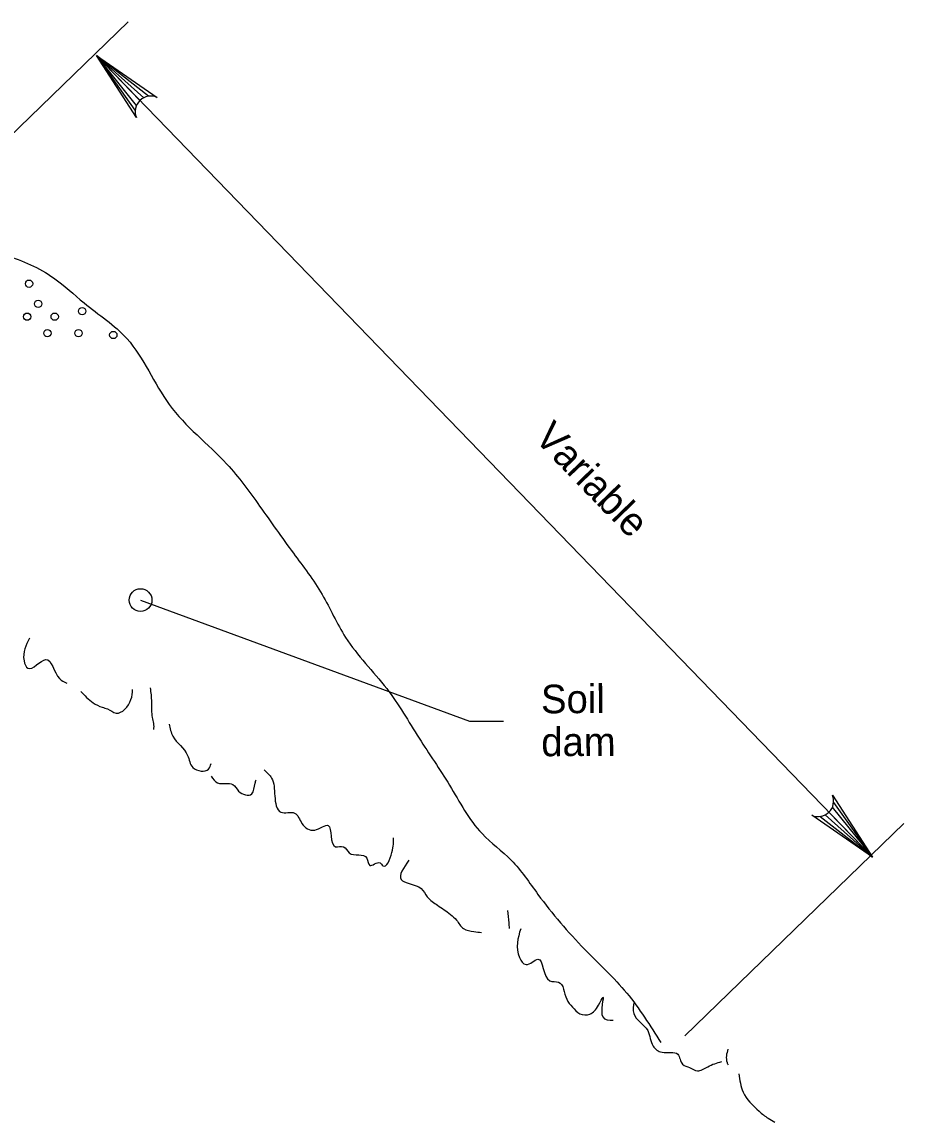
# Model space of a CAD drawing. Extents: x 3862.5 to 3891, y 3400.3 to 3419.7.
# Drawn here: x 3886.65 to 3890.97, y 3400.47 to 3405.86 of the extents above; entities that cross this region are included whole.
import ezdxf

# ---------------------------------------------------------------- set-up
doc = ezdxf.new("R2010")
doc.units = 0
doc.layers.add('DR_X_Trench_Drain', color=7, linetype='Continuous')
doc.layers.add('GT_X_Coal_Seam_1', color=7, linetype='Continuous')

msp = doc.modelspace()

# ---------------------------------------------------------------- linework, layer by layer
at = {"layer": 'DR_X_Trench_Drain'}
for centre, radius in [((3886.6838, 3404.5754), 0.0179), ((3886.7286, 3404.4768), 0.0179), ((3886.9439, 3404.4409), 0.0179), ((3886.6748, 3404.414), 0.0179), ((3886.8093, 3404.414), 0.0179), ((3886.7735, 3404.3333), 0.0179), ((3886.9259, 3404.3333), 0.0179), ((3887.0963, 3404.3243), 0.0179), ((3887.2295, 3403.0269), 0.0557)]:
    msp.add_circle(centre, radius, dxfattribs=at)
for points in [[(3882.5038, 3404.742), (3882.844, 3404.7208), (3883.6368, 3404.6299), (3884.1822, 3404.5789), (3884.7276, 3404.6302), (3885.5788, 3404.707), (3886.0457, 3404.7397), (3886.3113, 3404.759), (3886.569, 3404.715), (3886.8043, 3404.6035), (3886.9533, 3404.4814), (3887.1626, 3404.3064), (3887.3698, 3403.9842), (3887.6515, 3403.6928), (3887.8125, 3403.4869), (3887.9775, 3403.2565), (3888.1183, 3403.0547), (3888.233, 3402.8444), (3888.4342, 3402.5937), (3888.5931, 3402.351), (3888.742, 3402.1205), (3888.901, 3401.8839), (3889.0438, 3401.7537), (3889.1746, 3401.5865), (3889.404, 3401.3174), (3889.6092, 3401.1035), (3889.7762, 3400.8609)], [(3886.6853, 3402.8404), (3886.6592, 3402.7299), (3886.6773, 3402.6932), (3886.7658, 3402.7364), (3886.8322, 3402.6427), (3886.8685, 3402.6203)], [(3886.937, 3402.5797), (3886.9972, 3402.5247), (3887.0416, 3402.5024), (3887.0677, 3402.4943), (3887.11, 3402.474), (3887.1825, 3402.5397), (3887.1905, 3402.5888)], [(3887.277, 3402.5973), (3887.2831, 3402.5278), (3887.2871, 3402.4522), (3887.2931, 3402.4235), (3887.2931, 3402.3929)], [(3887.3696, 3402.4198), (3887.3877, 3402.3605), (3887.4601, 3402.2668), (3887.4862, 3402.2075), (3887.5627, 3402.1997), (3887.5748, 3402.2264)], [(3887.8343, 3402.1967), (3887.8706, 3402.1559), (3887.8867, 3402.068), (3887.9168, 3401.9884), (3887.9833, 3401.9847), (3888.0195, 3401.9337), (3888.0818, 3401.9012), (3888.1483, 3401.9239), (3888.1845, 3401.8198), (3888.2227, 3401.8199), (3888.251, 3401.7894), (3888.3375, 3401.7632), (3888.3515, 3401.7284), (3888.4018, 3401.7409), (3888.416, 3401.7267), (3888.4602, 3401.7923), (3888.4682, 3401.8638)], [(3887.5748, 3402.165), (3887.607, 3402.1324), (3887.6815, 3402.1245), (3887.7096, 3402.0919), (3887.774, 3402.0779), (3887.7901, 3402.131), (3887.7961, 3402.1474)], [(3888.5427, 3401.7537), (3888.5045, 3401.6595), (3888.6031, 3401.6149), (3888.6332, 3401.5742), (3888.6836, 3401.5334), (3888.746, 3401.4887), (3888.7761, 3401.4602), (3888.8103, 3401.4194), (3888.8606, 3401.4053), (3888.8988, 3401.3993)], [(3889.0257, 3401.5082), (3889.0317, 3401.4469), (3889.0337, 3401.4203)], [(3889.0901, 3401.4184), (3889.084, 3401.2773), (3889.1162, 3401.2427), (3889.1746, 3401.2695), (3889.2328, 3401.1634), (3889.2751, 3401.1574), (3889.3153, 3401.0738), (3889.3436, 3401.035), (3889.3797, 3401.0024), (3889.4281, 3401.0005), (3889.4703, 3401.0437), (3889.4925, 3401.0827), (3889.4925, 3400.9865), (3889.5427, 3400.9704)], [(3889.6455, 3401.0608), (3889.6435, 3401.0035), (3889.7118, 3400.9199), (3889.738, 3400.8444), (3889.7822, 3400.8139), (3889.8587, 3400.8039), (3889.8828, 3400.7549), (3889.9171, 3400.7388), (3889.9553, 3400.7225), (3890.0056, 3400.7432), (3890.074, 3400.768)], [(3890.1042, 3400.8294), (3890.1002, 3400.764), (3890.1062, 3400.7518)], [(3890.1586, 3400.709), (3890.1787, 3400.6192), (3890.2571, 3400.5254), (3890.3013, 3400.4908), (3890.3336, 3400.4725)]]:
    msp.add_spline(points, degree=3, dxfattribs=at)
at = {"layer": 'GT_X_Coal_Seam_1'}
for p, q in [((3886.0953, 3404.8174), (3887.1682, 3405.8562)), ((3887.0136, 3405.6922), (3890.8118, 3401.769)), ((3887.2268, 3405.4719), (3887.0136, 3405.6922)), ((3887.2101, 3405.4479), (3887.0136, 3405.6922)), ((3887.2037, 3405.4245), (3887.0136, 3405.6922)), ((3887.2453, 3405.4854), (3887.0136, 3405.6922)), ((3887.2688, 3405.493), (3887.0136, 3405.6922)), ((3890.6218, 3402.0365), (3890.8118, 3401.769)), ((3890.5566, 3401.9682), (3890.8118, 3401.769)), ((3890.5801, 3401.9758), (3890.8118, 3401.769)), ((3890.5987, 3401.9892), (3890.8118, 3401.769)), ((3890.6155, 3402.0133), (3890.8118, 3401.769)), ((3889.8935, 3400.8943), (3890.9663, 3401.933))]:
    msp.add_line(p, q, dxfattribs=at)
for points in [[(3887.2091, 3405.3884), (3887.0136, 3405.6922), (3887.3108, 3405.4869)], [(3887.2295, 3403.0269), (3888.8395, 3402.435), (3889.0055, 3402.435)], [(3890.6165, 3402.0727), (3890.8118, 3401.769), (3890.5146, 3401.9742)]]:
    msp.add_lwpolyline(points, dxfattribs=at)
for centre, start, end in [((3887.2799, 3405.4172), 66.1607, 201.9868), ((3890.5456, 3402.0439), 246.1607, 21.9868)]:
    msp.add_arc(centre, 0.0764, start, end, dxfattribs=at)

# ---------------------------------------------------------------- texts
for s, rotation, p in [('Variable', 314.0729, (3889.151, 3403.8164)), ('Soil', 0.3294, (3889.1901, 3402.4725)), ('dam', 0.3294, (3889.1913, 3402.2625))]:
    msp.add_text(s, height=0.14, rotation=rotation, dxfattribs=at).set_placement(p)

doc.saveas('drawing.dxf')
